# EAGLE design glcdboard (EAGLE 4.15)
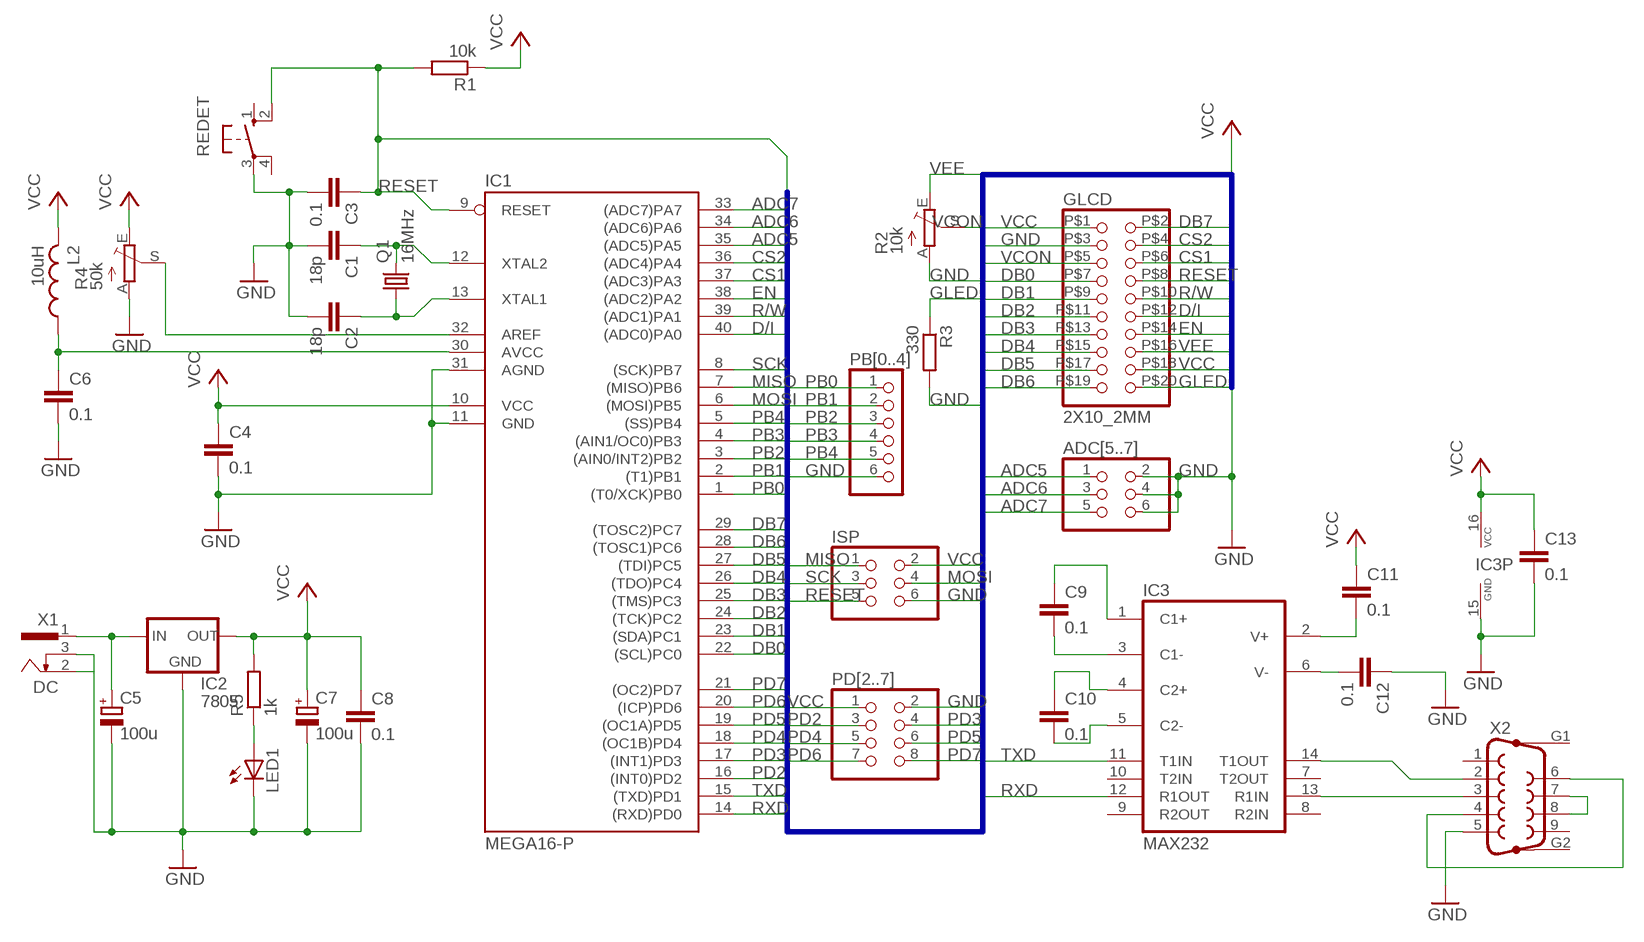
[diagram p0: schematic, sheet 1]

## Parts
ADC[5..7]  PINHD-2X3  [2X03]
C1  18p  C-EUC0805K  [C0805K]
C2  18p  C-EUC0805K  [C0805K]
C3  0.1  C-EUC0805K  [C0805K]
C4  0.1  C-EUC0805K  [C0805K]
C5  100u  CPOL-EUE5-8.5  [E5-8,5]
C6  0.1  C-EUC0805K  [C0805K]
C7  100u  CPOL-EUE5-8.5  [E5-8,5]
C8  0.1  C-EU025-025X050  [C025-025X050]
C9  0.1  C-EU025-025X050  [C025-025X050]
C10  0.1  C-EU025-025X050  [C025-025X050]
C11  0.1  C-EU025-025X050  [C025-025X050]
C12  0.1  C-EU025-025X050  [C025-025X050]
C13  0.1  C-EU025-025X050  [C025-025X050]
GLCD  2X10_2MM  [2X10_2MM]
IC1  MEGA16-P  [DIL40]
IC2  7805  78XXL  [78XXL]
IC3  MAX232  [DIL16]
ISP  PINHD-2X3  [2X03]
L2  10uH  L-US0207/5V  [0207/5V]
LED1  LED5MM  [LED5MM]
PB[0..4]  PINHD-1X6  [1X06]
PD[2..7]  PINHD-2X4  [2X04]
Q1  16MHz  CRYSTALHC49U70  [HC49U70]
R1  10k  R-EU_R0805  [R0805]
R2  10k  TRIM_EU-CA6H  [CA6H]
R3  330  R-EU_R0805  [R0805]
R4  50k  TRIM_EU-CA6H  [CA6H]
R5  1k  R-EU_0207/10  [0207/10]
REDET  10-XX  [B3F-10XX]
X1  DC  733980-62  [733980-62]
X2  F09HP  [F09HP]

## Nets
ADC5: ADC[5..7].1 IC1.35((ADC5)PA5)
ADC6: ADC[5..7].3 IC1.34((ADC6)PA6)
ADC7: ADC[5..7].5 IC1.33((ADC7)PA7)
CS1: GLCD.P$6 IC1.37((ADC3)PA3)
CS2: GLCD.P$4 IC1.36((ADC4)PA4)
D/I: GLCD.P$12 IC1.40((ADC0)PA0)
DB0: GLCD.P$7 IC1.22((SCL)PC0)
DB1: GLCD.P$9 IC1.23((SDA)PC1)
DB2: GLCD.P$11 IC1.24((TCK)PC2)
DB3: GLCD.P$13 IC1.25((TMS)PC3)
DB4: GLCD.P$15 IC1.26((TDO)PC4)
DB5: GLCD.P$17 IC1.27((TDI)PC5)
DB6: GLCD.P$19 IC1.28((TOSC1)PC6)
DB7: GLCD.P$2 IC1.29((TOSC2)PC7)
EN: GLCD.P$14 IC1.38((ADC2)PA2)
GLED: GLCD.P$20 R3.1
GND: ADC[5..7].2 ADC[5..7].4 ADC[5..7].6 C1.2 C2.2 C3.2 C4.2 C5.- C6.2 C7.- C8.2 C12.1 C13.2 GLCD.P$3 IC1.11(GND) IC1.31(AGND) IC2.GND IC3.15(GND) ISP.6 LED1.K(C) PB[0..4].6 PD[2..7].2 R2.A R3.2 R4.A REDET.3(P) X1.2 X1.3 X2.5
MISO: IC1.7((MISO)PB6) ISP.1
MOSI: IC1.6((MOSI)PB5) ISP.4
N$1: C2.1 IC1.13(XTAL1) Q1.1
N$2: C1.1 IC1.12(XTAL2) Q1.2
N$3: IC1.32(AREF) R4.S
N$4: C6.1 IC1.30(AVCC) L2.1
N$5: C5.+ IC2.IN X1.1
N$6: C9.1 IC3.1(C1+)
N$7: C9.2 IC3.3(C1-)
N$8: LED1.A R5.1
N$9: C10.1 IC3.4(C2+)
N$10: C10.2 IC3.5(C2-)
N$11: C11.2 IC3.2(V+)
N$12: C12.2 IC3.6(V-)
N$13: IC3.14(T1OUT) X2.2
N$14: IC3.13(R1IN) X2.3
N$15: X2.4 X2.6
N$16: X2.7 X2.8
PB0: IC1.1((T0/XCK)PB0) PB[0..4].1
PB1: IC1.2((T1)PB1) PB[0..4].2
PB2: IC1.3((AIN0/INT2)PB2) PB[0..4].3
PB3: IC1.4((AIN1/OC0)PB3) PB[0..4].4
PB4: IC1.5((SS)PB4) PB[0..4].5
PD2: IC1.16((INT0)PD2) PD[2..7].3
PD3: IC1.17((INT1)PD3) PD[2..7].4
PD4: IC1.18((OC1B)PD4) PD[2..7].5
PD5: IC1.19((OC1A)PD5) PD[2..7].6
PD6: IC1.20((ICP)PD6) PD[2..7].7
PD7: IC1.21((OC2)PD7) PD[2..7].8
R/W: GLCD.P$10 IC1.39((ADC1)PA1)
RESET: C3.1 GLCD.P$8 IC1.9(RESET) ISP.5 R1.2 REDET.2(S1)
RXD: IC1.14((RXD)PD0) IC3.12(R1OUT)
SCK: IC1.8((SCK)PB7) ISP.3
TXD: IC1.15((TXD)PD1) IC3.11(T1IN)
VCC: C4.1 C7.+ C8.1 C11.1 C13.1 GLCD.P$1 GLCD.P$18 IC1.10(VCC) IC2.OUT IC3.16(VCC) ISP.2 L2.2 PD[2..7].1 R1.1 R4.E R5.2
VCON: GLCD.P$5 R2.S
VEE: GLCD.P$16 R2.E
Unconnected: IC3.7(T2OUT) IC3.8(R2IN) IC3.9(R2OUT) IC3.10(T2IN) REDET.1(S) REDET.4(P1) X2.1 X2.9 X2.G1 X2.G2

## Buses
VCC,GND,VCON,DB[0..7],CS1,CS2,RESET,R/W,D/I,EN,VEE,GLED,MISO,SCK,RESET,MOSI,RXD,TXD,PB[0..4],PD[2..7],ADC[5..7]

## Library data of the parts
ADC[5..7] ISP = pinhead:PINHD-2X3: PIN HEADER
C1-C4 C6 C8-C13 = rcl:C-EU: CAPACITOR, European symbol
C5 C7 = rcl:CPOL-EU: POLARIZED CAPACITOR, European symbol
GLCD = 2x10_2mm:2X10_2MM
IC1 = atmel:MEGA16-P: MICROCONTROLLER 16 Kbytes FLASH 1 kbytes SRAM 512 bytes EEPROM USART 8-channel 10 bit ADC Source: avr.lbr
IC2 = v-reg:78XXL: VOLTAGE REGULATOR
IC3 = maxim:MAX232: RS232 TRANSEIVER
L2 = rcl:L-US: INDUCTOR, American symbol
LED1 = led:LED: LED
PB[0..4] = pinhead:PINHD-1X6: PIN HEADER
PD[2..7] = pinhead:PINHD-2X4: PIN HEADER
Q1 = crystal:CRYSTAL: CRYSTAL
R1 R3 R5 = rcl:R-EU_: RESISTOR, European symbol
R2 R4 = pot:TRIM_EU-: POTENTIOMETER
REDET = switch-omron:10-XX: OMRON SWITCH
X1 = con-conrad:73398?: FEMALE PRINT CONNECTOR Niedervolt-Steckverbinder Distributor Conrad
X2 = con-subd:F09HP: SUB-D

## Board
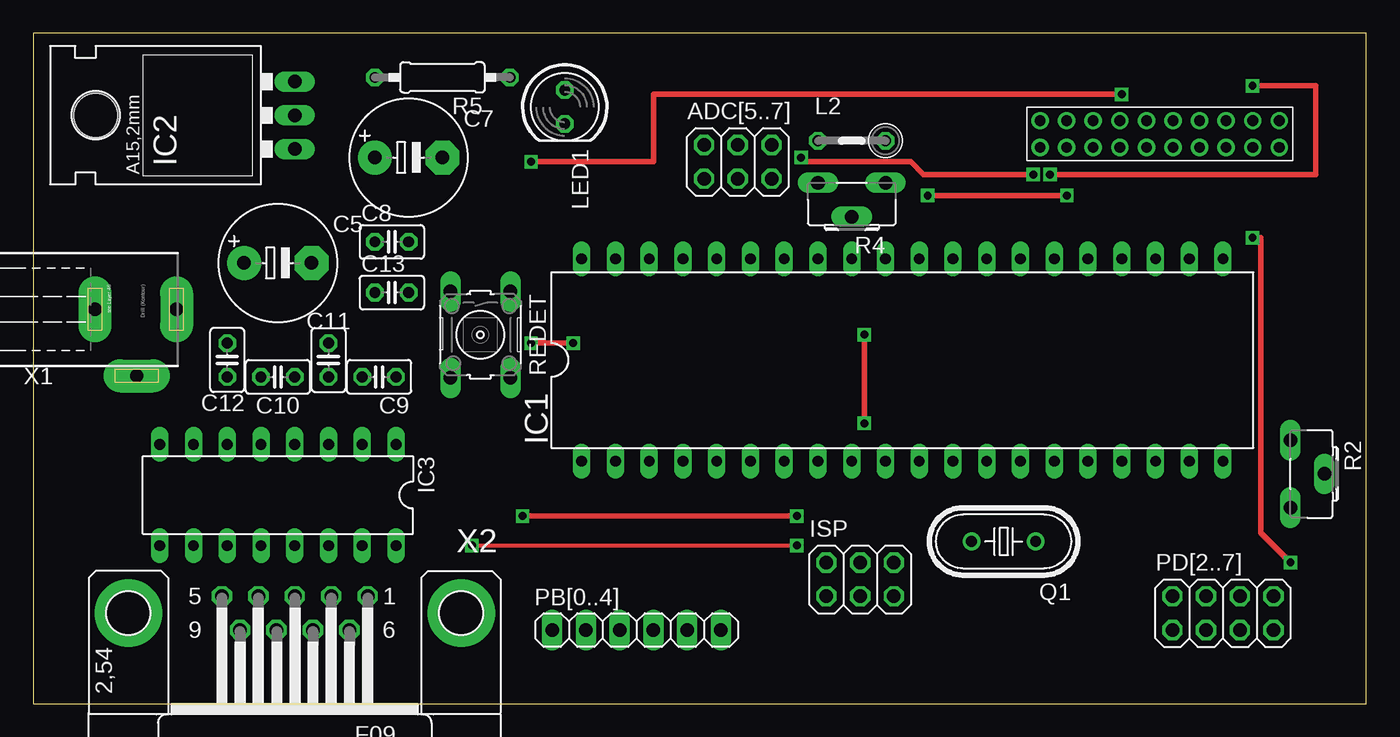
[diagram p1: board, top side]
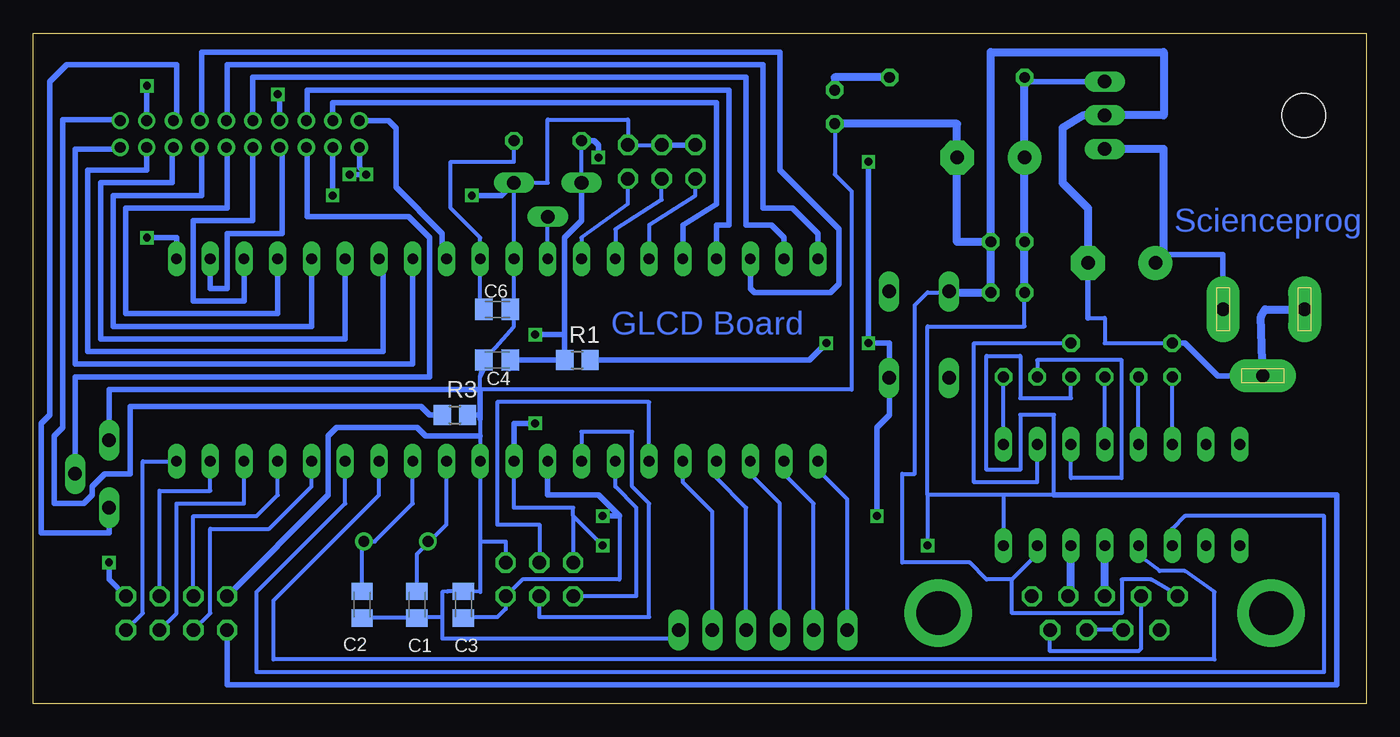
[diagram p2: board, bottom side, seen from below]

Size 100.31 x 50.47 mm. Coordinates in mm from the lower left corner, seen from the top.
Outline: 0,0 100.31,0 100.31,50.47 0,50.47 0,0
Copper layers (1*16): Top 0.035mm / dielectric 1.5mm / Bottom 0.035mm
Design rules "default": minimum track width 10mil, minimum drill 24mil, track to track 8mil, track to pad 8mil, pad to pad 8mil, via to via 8mil, smd to smd 8mil, copper to edge 40mil, drill to drill 8mil, minimum pad ring 10mil, minimum via ring 8mil, stop-mask expansion 4mil, vias tented up to drill 0mil, thermal gap 10mil

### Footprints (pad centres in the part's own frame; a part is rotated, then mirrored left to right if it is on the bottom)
2X03 = drill 1.016 octagon: 1 -2.54,-1.27; 2 -2.54,1.27; 3 0,-1.27; 4 0,1.27; 5 2.54,-1.27; 6 2.54,1.27
C0805K = smd 1.3 x 1.6: 1 -1,0; 2 1,0
E5-8,5 = drill 1.016 pad 2.54 round: + -2.54,0 | drill 1.016 pad 2.54 octagon: - 2.54,0
C025-025X050 = drill 0.813 octagon: 1 -1.27,0; 2 1.27,0
2X10_2MM = drill 0.8 round: P$1 -9,3; P$2 -9,5; P$3 -7,3; P$4 -7,5; P$5 -5,3; P$6 -5,5; P$7 -3,3; P$8 -3,5; P$9 -1,3; P$10 -1,5; P$11 1,3; P$12 1,5; P$13 3,3; P$14 3,5; P$15 5,3; P$16 5,5; P$17 7,3; P$18 7,5; P$19 9,3; P$20 9,5
DIL40 = drill 0.813 long: 1 -24.13,-7.62; 2 -21.59,-7.62; 3 -19.05,-7.62; 4 -16.51,-7.62; 5 -13.97,-7.62; 6 -11.43,-7.62; 7 -8.89,-7.62; 8 -6.35,-7.62; 9 -3.81,-7.62; 10 -1.27,-7.62; 11 1.27,-7.62; 12 3.81,-7.62; 13 6.35,-7.62; 14 8.89,-7.62; 15 11.43,-7.62; 16 13.97,-7.62; 17 16.51,-7.62; 18 19.05,-7.62; 19 21.59,-7.62; 20 24.13,-7.62; 21 24.13,7.62; 22 21.59,7.62; 23 19.05,7.62; 24 16.51,7.62; 25 13.97,7.62; 26 11.43,7.62; 27 8.89,7.62; 28 6.35,7.62; 29 3.81,7.62; 30 1.27,7.62; 31 -1.27,7.62; 32 -3.81,7.62; 33 -6.35,7.62; 34 -8.89,7.62; 35 -11.43,7.62; 36 -13.97,7.62; 37 -16.51,7.62; 38 -19.05,7.62; 39 -21.59,7.62; 40 -24.13,7.62
78XXL = drill 1.016 long: GND 0,-3.81; IN -2.54,-3.81; OUT 2.54,-3.81 | hole 3.302: 0,11.176
DIL16 = drill 0.813 long: 1 -8.89,-3.81; 2 -6.35,-3.81; 3 -3.81,-3.81; 4 -1.27,-3.81; 5 1.27,-3.81; 6 3.81,-3.81; 7 6.35,-3.81; 8 8.89,-3.81; 9 8.89,3.81; 10 6.35,3.81; 11 3.81,3.81; 12 1.27,3.81; 13 -1.27,3.81; 14 -3.81,3.81; 15 -6.35,3.81; 16 -8.89,3.81
0207/5V = drill 0.813 octagon: 1 -2.54,0; 2 2.54,0
LED5MM = drill 0.813 octagon: A -1.27,0; K 1.27,0
1X06 = drill 1.016 long: 1 -6.35,0; 2 -3.81,0; 3 -1.27,0; 4 1.27,0; 5 3.81,0; 6 6.35,0
2X04 = drill 1.016 octagon: 1 -3.81,-1.27; 2 -3.81,1.27; 3 -1.27,-1.27; 4 -1.27,1.27; 5 1.27,-1.27; 6 1.27,1.27; 7 3.81,-1.27; 8 3.81,1.27
HC49U70 = drill 0.813 round: 1 -2.413,0; 2 2.413,0
R0805 = smd 1.3 x 1.5: 1 -0.95,0; 2 0.95,0
CA6H = drill 1.016 long: A -2.54,0; E 2.54,0; S 0,2.54
0207/10 = drill 0.813 octagon: 1 -5.08,0; 2 5.08,0
B3F-10XX = drill 1.016 long: 1 -3.251,2.261; 2 3.251,2.261; 3 -3.251,-2.261; 4 3.251,-2.261
733980-62 = drill 1 pad 2.5 long: 1 0,8.57; 2 0,2.42; 3 5,5.57
F09HP = drill 1.016 octagon: 1 -5.486,-1.27; 2 -2.743,-1.27; 3 0,-1.27; 4 2.743,-1.27; 5 5.486,-1.27; 6 -4.115,1.27; 7 -1.372,1.27; 8 1.372,1.27; 9 4.115,1.27 | drill 3.302 pad 5.08 round: G1 -12.522,0; G2 12.522,0

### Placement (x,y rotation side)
ADC[5..7]  53.02,40.79 0 top
C1  71.43,7.46 270 bottom
C2  75.56,7.46 270 bottom
C3  67.94,7.46 90 bottom
C4  65.4,25.87 180 bottom
C5  18.41,33.17 0 top
C6  65.4,29.68 0 bottom
C7  28.25,41.11 0 top
C8  26.98,34.76 0 top
C9  26.03,24.6 180 top
C10  18.41,24.6 180 top
C11  22.22,25.87 90 top
C12  14.6,25.87 270 top
C13  26.98,30.95 0 top
GLCD  84.77,38.89 0 top
IC1  65.4,25.87 0 top
IC2  15.87,44.28 90 top
IC3  18.41,15.71 180 top
ISP  62.23,9.36 0 top
L2  61.59,42.38 180 top
LED1  40,44.92 270 top
PB[0..4]  45.4,5.55 0 top
PD[2..7]  89.53,6.82 0 top
Q1  73.02,12.22 180 top
R1  59.37,25.87 0 bottom
R2  94.61,17.3 270 top
R3  68.57,21.74 0 bottom
R4  61.59,39.2 180 top
R5  30.79,47.14 180 top
REDET  33.65,27.77 270 top
X1  2.22,29.68 270 top
X2  19.68,6.82 180 top

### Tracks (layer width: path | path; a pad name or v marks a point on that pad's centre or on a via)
ADC5
  Bottom 0.305: ADC[5..7].1 50.48,38.25 53.97,36.03 IC1.35
ADC6
  Bottom 0.305: ADC[5..7].3 53.02,37.94 56.51,35.71 IC1.34
ADC7
  Bottom 0.305: ADC[5..7].5 55.56,37.62 59.05,35.08 IC1.33
CS1
  Bottom 0.406: IC1.37 48.89,36.03 47.94,36.03 47.94,46.19 79.69,46.19 79.69,43.97 GLCD.P$6
CS2
  Bottom 0.406: IC1.36 51.43,36.03 48.89,37.62 48.89,45.24 77.78,45.24 77.78,43.97 77.77,43.95 GLCD.P$4
D/I
  Bottom 0.406: IC1.40 41.27,35.39 43.18,37.3 45.4,37.3 45.4,48.09 85.72,48.09 85.72,43.97 85.77,43.92 GLCD.P$12
DB0
  Bottom 0.406: IC1.22 86.99,31.27 85.72,31.27 85.72,35.39 81.59,35.39 81.59,41.89 GLCD.P$7
DB1
  Bottom 0.406: IC1.23 84.45,30.31 88.26,30.31 88.26,36.35 83.81,36.35 83.81,41.89 GLCD.P$9
DB2
  Bottom 0.406: IC1.24 81.91,29.36 93.34,29.36 93.34,37.3 85.72,37.3 85.72,41.89 GLCD.P$11
DB3
  Bottom 0.406: IC1.25 79.37,28.41 94.29,28.41 94.29,38.25 87.62,38.25 87.62,41.89 | 87.62,41.89 87.62,42.06 | 87.62,41.89 GLCD.P$13
DB4
  Bottom 0.406: IC1.26 76.83,27.46 95.24,27.46 95.24,39.2 89.85,39.2 89.85,41.89 GLCD.P$15
DB5
  Bottom 0.406: IC1.27 73.97,33.49 73.97,26.5 96.2,26.5 96.2,40.16 91.75,40.16 91.75,41.89 GLCD.P$17
DB6
  Bottom 0.406: IC1.28 71.75,25.55 97.15,25.55 97.15,41.74 93.66,41.74 93.66,41.89 GLCD.P$19
DB7
  Bottom 0.406: GLCD.P$2 73.57,43.89 73.02,43.33 73.02,38.89 69.53,35.39 69.53,33.81 IC1.29
EN
  Bottom 0.406: IC1.38 46.35,31.27 46.03,30.95 40.32,30.95 39.68,31.58 39.68,35.71 44.13,40.16 44.13,49.05 87.62,49.05 87.62,43.97 87.7,43.89 GLCD.P$14
GLED
  Bottom 0.406: R3.1 70.48,21.74 71.11,22.38 93.02,22.38 93.02,17.3 94.93,17.3 95.88,16.34 95.88,15.71 96.52,15.08 98.74,15.08 98.74,20.15 98.1,20.79 98.1,43.97 93.66,43.97 93.74,43.89 GLCD.P$20
GND  (via drill 0.6)
  Top 0.406: v67.3,38.25 v77.78,38.25
  Bottom 0.305: ADC[5..7].4 ADC[5..7].6 55.56,43.97 61.59,43.97 61.59,39.2 R4.A IC1.31 64.13,29.36 | ISP.6 64.77,12.22 66.67,12.22 | 66.67,12.22 IC1.11 66.67,20.15 66.67,21.74 | 66.67,24.6 66.35,25.23 | 64.13,29.36 C6.2 | 64.13,29.36 64.13,29.04 | 64.13,29.36 64.13,28.41 66.35,25.87 66.67,24.6 | 66.67,24.6 C4.2 | 66.67,24.6 66.67,23.65 38.73,23.65 38.73,38.57 40,39.84 LED1.K | X2.5 14.19,8.18 16.19,9.36 18.41,9.36 18.41,6.82 26.66,6.82 26.66,9.36 | C12.1 19.68,27.14 19.68,29.04 20.95,29.04 | 31.43,30.95 31.39,30.99 REDET.3 31.39,31.23 31.43,31.27 31.74,30.95 33.02,30.95 33.97,30 33.97,17.3 34.92,17.3 34.92,10.63 29.84,10.63 28.57,9.36 26.66,9.36 | IC3.15 24.76,11.27 26.66,9.36 | 66.67,12.22 66.67,8.41 C3.2 69.16,8.46 69.53,8.41 69.53,6.5 | 69.53,6.5 71.43,6.5 C1.2 75.51,6.46 75.56,6.5 C2.2 | PB[0..4].6 51.75,4.92 69.53,4.92 69.53,6.5
  Bottom 0.406: ADC[5..7].4 ADC[5..7].2 | R2.A 94.61,23.65 66.67,23.65 66.67,21.74 | 66.67,21.74 R3.2 | 66.67,21.74 66.67,21.42 | PD[2..7].2 78.1,15.71 78.1,20.15 77.46,20.79 71.43,20.79 70.8,20.15 66.67,20.15 | GLCD.P$3 77.77,39.22 v77.78,38.25 | v67.3,38.25 65.08,38.25 R4.A | X1.3 11.19,24.68 13.65,27.14 C12.1 | C5.- 20.95,29.04
  Bottom 0.61: X1.3 7.93,29.12 7.62,29.68 X1.2 | LED1.K 30.79,43.65 C7.- 30.79,34.76 C8.2 | C8.2 C13.2 31.43,30.95 | C8.2 28.25,49.05 15.24,49.05 15.24,44.28 IC2.GND 21.27,44.28 22.86,43.33 22.86,39.2 20.95,37.3 C5.-
MISO
  Bottom 0.305: IC1.7 56.51,16.34 54.92,14.76 54.92,8.09 ISP.1
MOSI
  Bottom 0.305: IC1.6 53.97,22.7 65.4,22.7 65.4,13.49 62.23,13.49 ISP.4
N$1
  Bottom 0.305: IC1.13 71.75,15.08 74.61,12.22 Q1.1 75.56,12.22 C2.1
N$2
  Bottom 0.305: IC1.12 69.21,13.49 70.48,12.22 | 70.48,12.22 Q1.2 | C1.1 71.43,11.27 70.48,12.22
N$3
  Bottom 0.305: IC1.32 R4.S
N$4
  Bottom 0.305: L2.1 64.13,40.79 68.89,40.79 68.89,37.3 66.67,35.08 IC1.30 66.67,30.31 | C6.1 66.67,30.31 | 66.67,30.31 66.67,29.04
N$5
  Bottom 0.406: C5.+ 15.24,33.17 15.24,33.49 14.92,33.81 10.79,33.81 10.79,33.8 X1.1
  Bottom 0.61: IC2.IN 15.24,41.74 15.24,33.49
N$6
  Bottom 0.305: IC3.1 C9.1
N$7
  Bottom 0.305: C9.2 24.76,25.87 18.41,25.87 18.41,16.98 22.22,16.98 IC3.3
N$8
  Bottom 0.61: R5.1 40,47.14 LED1.A
N$9
  Bottom 0.305: IC3.4 C10.1
N$10
  Bottom 0.305: IC3.5 C10.2
N$11
  Bottom 0.305: C11.2 29.52,27.14 29.52,16.66 24.76,16.66 IC3.2 24.76,19.84
N$12
  Bottom 0.305: IC3.6 C12.2
N$13
  Bottom 0.61: X2.2 22.22,8.09 IC3.14
N$14
  Bottom 0.61: X2.3 IC3.13
N$15
  Bottom 0.305: X2.4 16.94,4.17 17.14,3.96 23.81,3.96 23.81,5.55 X2.6
N$16
  Bottom 0.305: X2.8 X2.7
PB0
  Bottom 0.305: IC1.1 41.27,17.61 39.05,15.39 PB[0..4].1
PB1
  Bottom 0.305: IC1.2 43.81,17.3 41.59,15.08 PB[0..4].2
PB2
  Bottom 0.305: IC1.3 46.35,17.3 44.13,15.08 PB[0..4].3
PB3
  Bottom 0.305: IC1.4 48.89,16.98 46.67,14.76 PB[0..4].4
PB4
  Bottom 0.305: IC1.5 51.43,16.66 49.21,14.44 PB[0..4].5
PD2
  Bottom 0.305: IC1.16 79.37,16.34 82.55,13.17 86.99,13.17 86.99,6.82 PD[2..7].3
PD3
  Bottom 0.305: IC1.17 81.91,15.71 83.5,14.12 88.26,14.12 PD[2..7].4
PD4
  Bottom 0.305: IC1.18 84.45,15.08 89.53,15.08 89.53,6.82 PD[2..7].5
PD5
  Bottom 0.305: IC1.19 86.99,16.03 90.8,16.03 PD[2..7].6
PD6
  Bottom 0.305: IC1.20 92.07,18.25 92.07,6.82 PD[2..7].7
PD7  (via drill 0.6)
  Top 0.406: v91.75,35.08 92.39,35.08 92.39,12.85 v94.61,10.63
  Bottom 0.406: IC1.21 89.53,35.08 v91.75,35.08 | v94.61,10.63 94.61,9.36 PD[2..7].8
R/W
  Bottom 0.406: IC1.39 43.81,35.08 44.76,36.03 46.67,36.03 46.67,47.14 83.81,47.14 83.81,43.97 83.77,43.92 GLCD.P$10
RESET  (via drill 0.6)
  Top 0.406: v37.46,27.14 v40.64,27.14 | v36.83,14.12 v57.46,14.12 | v81.91,45.87 46.67,45.87 46.67,40.79 v37.46,40.79
  Bottom 0.305: 56.19,14.12 56.19,9.36 63.5,9.36 ISP.5 64.77,7.14 65.4,6.5 67.94,6.5 C3.1
  Bottom 0.406: R1.2 41.91,25.87 v40.64,27.14 | 35.87,24.6 35.87,27.14 v37.46,27.14 v37.46,40.79 | IC1.9 61.59,15.71 57.78,15.71 56.19,14.12 v57.46,14.12 | v36.83,14.12 36.83,20.79 35.87,21.74 35.87,24.6 | 35.87,24.6 35.91,24.56 REDET.2 | GLCD.P$8 81.77,45.73 v81.91,45.87
RXD
  Bottom 0.305: IC3.12 16.82,10.95 15.55,10 13.65,10 11.43,8.41 11.43,3.33 82.23,3.33 82.23,7.77 74.29,15.71 IC1.14
SCK
  Bottom 0.305: IC1.8 59.05,20.47 55.24,20.47 55.24,16.34 53.97,15.08 53.97,6.5 62.23,6.5 ISP.3
TXD
  Bottom 0.305: IC3.11 14.6,13.17 13.65,14.12 3.17,14.12 3.17,2.38 83.5,2.38 83.5,8.41 76.83,15.08 IC1.15
VCC  (via drill 0.6)
  Top 0.305: v33.02,11.9 v57.46,11.9
  Top 0.406: v75.24,39.84 66.99,39.84 66.03,40.79 58.1,40.79 v57.78,41.11 | v91.75,46.51 96.52,46.51 96.52,39.84 v76.51,39.84 | v62.54,21.11 v62.54,27.77
  Bottom 0.305: C11.1 22.22,23.01 26.03,23.01 26.03,26.19 28.57,26.19 28.57,17.61 26.03,17.61 26.03,21.74 23.49,21.74 23.49,15.71 27.3,15.71 | 27.3,15.71 IC3.16 | R4.E L2.2 | IC1.10 64.13,14.76 59.69,14.76 59.69,14.12 | 59.69,14.12 ISP.2 | C13.1 25.71,28.41 33.02,28.41 33.02,15.71 | 27.3,15.71 33.02,15.71 | 33.02,15.71 v33.02,11.9 | v57.46,11.9 59.69,14.12
  Bottom 0.406: PD[2..7].1 85.72,1.42 2.22,1.42 2.22,15.71 23.49,15.71 | R4.E 59.05,36.35 60.32,35.08 60.32,27.77 | 60.32,27.77 R1.1 C4.1 64.45,25.23 | GLCD.P$1 75.77,40.37 v75.24,39.84 v76.51,39.84 | v57.78,41.11 57.78,42.06 58.1,42.38 L2.2 | GLCD.P$18 91.77,46.49 v91.75,46.51 | IC1.10 64.13,21.11 v62.54,21.11 | v62.54,27.77 60.32,27.77 | 25.71,46.82 IC2.OUT
  Bottom 0.61: R5.2 25.71,46.82 C7.+ C8.1 C13.1
VCON
  Bottom 0.406: R2.S 97.15,24.6 70.48,24.6 70.48,35.08 72.07,36.66 79.69,36.66 79.69,41.74 79.77,41.82 GLCD.P$5
VEE
  Bottom 0.406: R2.E 94.61,12.85 99.69,12.85 99.69,21.11 99.05,21.74 99.05,46.82 97.78,48.09 89.53,48.09 89.53,44.28 89.85,43.97 GLCD.P$16

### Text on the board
Bottom: Scienceprog | GLCD Board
